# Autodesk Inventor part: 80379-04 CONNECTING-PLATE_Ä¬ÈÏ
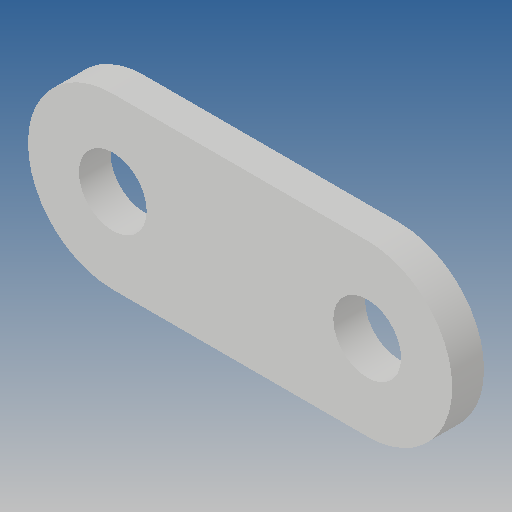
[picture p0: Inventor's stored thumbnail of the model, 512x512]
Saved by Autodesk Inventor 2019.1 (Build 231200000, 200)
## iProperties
Created: 2010-06
Part Number: 80379-04 CONNECTING-PLATE_Ä¬ÈÏ
Material: Ogólny
Document SubType Name: Modeling
Designer: CADENGINEERING4
Density: 1 g/cm^3
Appearance: Domyślna
Author: CADENGINEERING4
Revision Number: ÈÎºÎ
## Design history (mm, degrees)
feature "NONE"
node "Bryła1"
